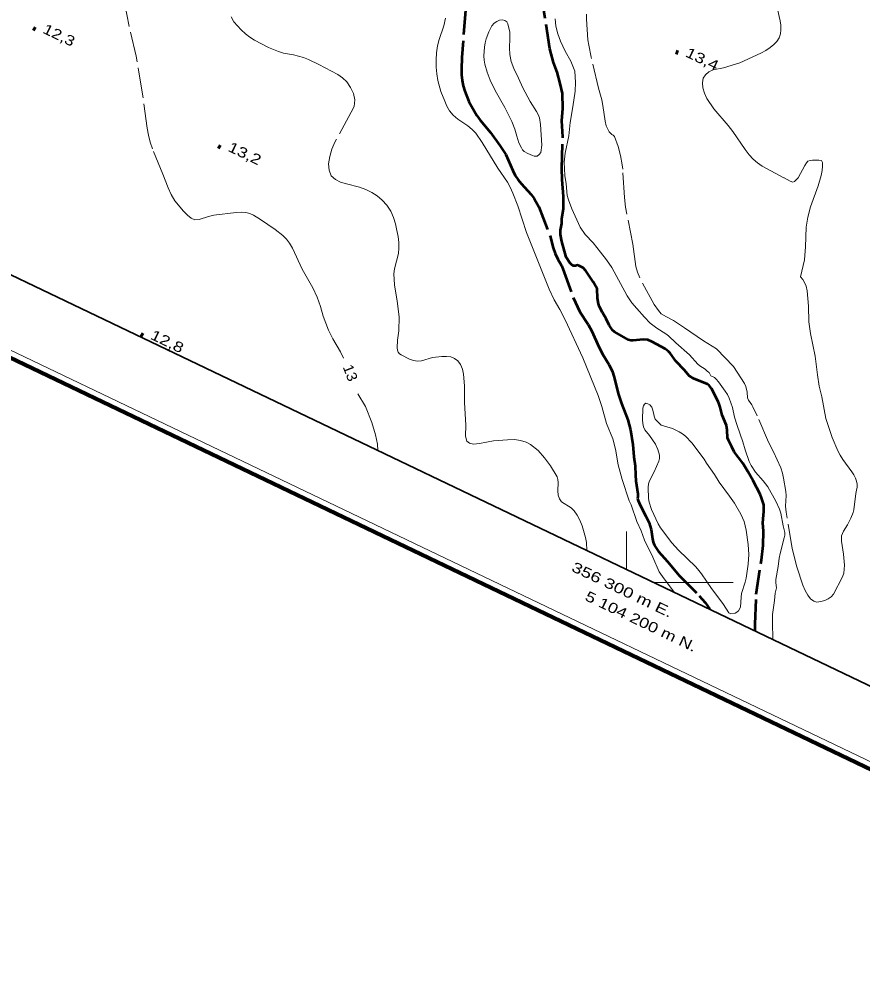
# Model space of a CAD drawing. Extents: x 355726 to 357533, y 5103782 to 5105258.
# Drawn here: x 356210.9 to 356334.6, y 5104143.5 to 5104282.7 of the extents above; entities that cross this region are included whole.
import ezdxf
from ezdxf.enums import TextEntityAlignment as Align

# ---------------------------------------------------------------- set-up
doc = ezdxf.new("R2010")
doc.units = 0
doc.header["$LTSCALE"] = 0.6
doc.linetypes.add('LONG_DASHED', pattern=[7.5, 6, -1.5])
for name, color, linetype, lineweight in [('1', 7, 'LONG_DASHED', 53), ('2', 7, 'LONG_DASHED', 13), ('3', 7, 'Continuous', 140), ('60', 7, 'Continuous', 13), ('61', 7, 'Continuous', 13)]:
    doc.layers.add(name, color=color, linetype=linetype, lineweight=lineweight)

msp = doc.modelspace()

# ---------------------------------------------------------------- linework, layer by layer
at = {"layer": '1'}
for points in [[(356290.52, 5104252.71), (356290.54, 5104253.4), (356290.78, 5104254.91), (356290.75, 5104256.67), (356290.56, 5104259.13), (356290.53, 5104260.76), (356290.66, 5104265.43), (356290.54, 5104267.75), (356290.65, 5104269.57), (356290.61, 5104271.76), (356290.3, 5104273.26), (356289.86, 5104274.9), (356289.3, 5104276.32), (356288.76, 5104278.34), (356287.53, 5104286.45)], [(356276.37, 5104284), (356275.85, 5104277.04), (356275.79, 5104275.34), (356275.83, 5104274.51), (356275.92, 5104273.68), (356276.07, 5104272.88), (356276.28, 5104272.11), (356276.87, 5104270.62), (356278.06, 5104268.53), (356278.52, 5104267.87), (356280.07, 5104266.05), (356281.44, 5104264.16), (356282.29, 5104262.8), (356283.32, 5104260.49), (356283.69, 5104259.76), (356284.1, 5104259.12), (356284.57, 5104258.55), (356286.03, 5104256.94), (356286.45, 5104256.37), (356287.13, 5104255.15), (356288.81, 5104250.82), (356289.27, 5104249.12), (356289.54, 5104248.32), (356289.94, 5104247.44), (356290.46, 5104246.53), (356290.68, 5104246.05), (356292.2, 5104241.84), (356293.19, 5104239.76), (356294.39, 5104237.87), (356294.94, 5104236.88), (356295.93, 5104234.59), (356296.55, 5104233.46), (356297.48, 5104231.96), (356297.98, 5104230.92), (356298.17, 5104230.3), (356298.82, 5104227.63), (356299.28, 5104226.3), (356300.2, 5104223.9), (356300.58, 5104222.43), (356300.93, 5104220.29), (356301.11, 5104218.48), (356301.3, 5104217.16)], [(356318.91, 5104192.9), (356318.9, 5104193.93), (356319.06, 5104198.3), (356319.81, 5104203.29), (356320.04, 5104205.44), (356320.1, 5104207.55), (356320.03, 5104208.79), (356320.09, 5104209.92), (356320.18, 5104210.45), (356320.14, 5104211.42), (356319.83, 5104212.46), (356319.61, 5104212.99), (356318.58, 5104214.96), (356317.82, 5104216.33), (356317.07, 5104217.51), (356315.82, 5104219.2), (356315.49, 5104219.93), (356314.96, 5104220.9), (356314.85, 5104221.25), (356314.78, 5104222.38), (356314.66, 5104223.07), (356314.03, 5104224.59), (356313.76, 5104225.76), (356313.51, 5104226.48), (356312.47, 5104228.47), (356312.15, 5104228.92), (356311.89, 5104229.11), (356309.83, 5104229.97)], [(356301.3, 5104217.16), (356301.33, 5104215.78), (356301.4, 5104214.93), (356301.67, 5104213.05), (356301.69, 5104212.65), (356301.65, 5104212.3), (356301.98, 5104211.45), (356302.87, 5104209.78), (356303.33, 5104208.79), (356303.64, 5104207.8), (356303.82, 5104206.41), (356303.93, 5104205.95), (356304.14, 5104205.46), (356304.4, 5104205), (356304.73, 5104204.55), (356306.02, 5104203.09), (356307.72, 5104201.04), (356310.68, 5104198.08), (356311.56, 5104197.09), (356312.23, 5104196.09)]]:
    msp.add_lwpolyline(points, dxfattribs=at)
at = {"layer": '1', "linetype": 'Continuous'}
msp.add_lwpolyline([(356309.83, 5104229.97), (356309.23, 5104230.34), (356308.53, 5104231.19), (356307.26, 5104232.49), (356306.41, 5104233.65), (356306.17, 5104233.91), (356305.69, 5104234.3), (356303.79, 5104235.34), (356303.15, 5104235.63), (356302.45, 5104235.66), (356301, 5104235.51), (356300.65, 5104235.55), (356300.33, 5104235.65), (356298.27, 5104236.79), (356297.97, 5104237.04), (356297.47, 5104237.78), (356297.05, 5104238.72), (356296.49, 5104239.63), (356296.05, 5104240.48), (356295.91, 5104240.9), (356295.75, 5104241.73), (356295.7, 5104243.13), (356295.12, 5104244.16), (356294.05, 5104245.75), (356293.65, 5104246.19), (356293.05, 5104246.51), (356292.8, 5104246.57), (356292.51, 5104246.49), (356292.22, 5104246.49), (356291.97, 5104246.63), (356291.69, 5104246.91), (356291.18, 5104247.78), (356290.55, 5104250.05), (356290.35, 5104251.07), (356290.34, 5104251.71), (356290.52, 5104252.71)], dxfattribs=at)
at = {"layer": '2'}
for points in [[(356258.48, 5104232.94), (356258.06, 5104233.88), (356256.94, 5104235.76), (356256.28, 5104237.05), (356255.51, 5104239.09), (356255.11, 5104240.51), (356254.64, 5104241.9), (356254.01, 5104243.24), (356252.45, 5104246.01), (356251.01, 5104249.09), (356250.59, 5104249.8), (356250.11, 5104250.4), (356249.58, 5104250.92), (356248.46, 5104251.83), (356246.33, 5104253.3), (356245.3, 5104253.9), (356244.76, 5104254.15), (356244.18, 5104254.3), (356243.52, 5104254.34), (356242.76, 5104254.32), (356239.45, 5104253.9), (356238.69, 5104253.71), (356237.31, 5104253.26), (356236.69, 5104253.22), (356236.14, 5104253.46), (356235.59, 5104253.92), (356235, 5104254.53), (356233.75, 5104256.01), (356233.2, 5104256.96), (356232.76, 5104257.92), (356232.01, 5104259.92), (356230.48, 5104263.63), (356230.14, 5104264.63), (356229.91, 5104265.67), (356229.7, 5104266.7), (356228.98, 5104271.99), (356228.1, 5104277.25), (356227.05, 5104281.59), (356226.34, 5104285.21)], [(356321.91, 5104285.23), (356322.58, 5104282.45), (356322.65, 5104281.78), (356322.66, 5104281.13), (356322.6, 5104280.51), (356322.4, 5104279.94), (356322.08, 5104279.41), (356321.63, 5104278.95), (356321.09, 5104278.51), (356320.43, 5104278.09), (356319.7, 5104277.71), (356316.62, 5104276.25), (356314.24, 5104275.55), (356312.71, 5104275.23), (356312.08, 5104274.96), (356311.59, 5104274.53), (356311.27, 5104274), (356311.16, 5104273.32), (356311.23, 5104272.59), (356311.44, 5104271.83), (356311.8, 5104271.05), (356312.84, 5104269.53), (356314.94, 5104267.09), (356315.61, 5104266.19), (356317.41, 5104263.54), (356318, 5104262.79), (356318.59, 5104262.13), (356319.25, 5104261.59), (356319.93, 5104261.13), (356323.16, 5104259.38), (356324.02, 5104258.93), (356324.41, 5104258.78), (356324.64, 5104258.88), (356324.91, 5104259.08), (356325.19, 5104259.38), (356326.19, 5104261.21), (356326.41, 5104261.58), (356326.64, 5104261.82), (356326.94, 5104261.93), (356327.31, 5104261.98), (356328.25, 5104262.01), (356328.6, 5104261.94), (356328.76, 5104261.63), (356328.79, 5104261.11), (356328.73, 5104260.49), (356328.56, 5104259.76), (356328.12, 5104258.22), (356327.01, 5104255.13), (356326.62, 5104253.63), (356326.38, 5104252.15), (356326.29, 5104249.26), (356326.11, 5104247.38), (356325.52, 5104244.88), (356325.87, 5104244.48), (356326.14, 5104244.05)], [(356241.99, 5104283), (356242.39, 5104282.3), (356243.49, 5104281.09), (356244.11, 5104280.53), (356244.75, 5104280.04), (356245.42, 5104279.61), (356247.49, 5104278.53), (356248.94, 5104277.93), (356249.69, 5104277.71), (356251.18, 5104277.45), (356252.61, 5104277.04), (356253.36, 5104276.74), (356254.86, 5104276.04), (356257.68, 5104274.55), (356258.35, 5104274.09), (356258.96, 5104273.46), (356259.51, 5104272.67), (356259.94, 5104271.75), (356260.15, 5104270.83), (356260.04, 5104269.88), (356259.64, 5104269.01), (356257.23, 5104264.61), (356256.8, 5104263.61), (356256.47, 5104262.53), (356256.31, 5104261.46), (356256.39, 5104260.5)], [(356305.9, 5104239.01), (356305.09, 5104239.46), (356304.7, 5104239.91), (356304.09, 5104240.79), (356301.96, 5104244.74), (356301.63, 5104245.55), (356301.38, 5104246.38), (356300.92, 5104249.66), (356299.88, 5104255.11), (356299.73, 5104256.53), (356299.46, 5104260.65), (356299.39, 5104261.3), (356299.11, 5104262.66), (356298.77, 5104264.01), (356298.26, 5104265.44), (356298.07, 5104265.66), (356297.85, 5104265.78), (356297.47, 5104266.17), (356297.05, 5104267.05), (356296.87, 5104267.7), (356296.54, 5104270.03), (356296.37, 5104270.86), (356295.92, 5104272.55), (356294.85, 5104277.09), (356294.48, 5104278.84), (356294.36, 5104279.66), (356294.12, 5104282.68), (356294.15, 5104283.4)], [(356256.39, 5104260.5), (356256.7, 5104259.71), (356257.31, 5104259.15), (356258.06, 5104258.78), (356258.92, 5104258.5), (356260.82, 5104258.01), (356261.78, 5104257.7), (356262.64, 5104257.26), (356263.44, 5104256.75), (356264.19, 5104256.13), (356264.87, 5104255.38), (356265.43, 5104254.51), (356265.82, 5104253.59), (356266.13, 5104252.63), (356266.34, 5104251.68), (356266.51, 5104250.78), (356266.6, 5104249.91), (356266.62, 5104249.07), (356266.58, 5104248.29), (356266, 5104246.05), (356265.9, 5104245.29), (356265.96, 5104243.7), (356266.37, 5104241.3), (356266.64, 5104239.01), (356266.63, 5104236.95), (356266.44, 5104235.59), (356266.36, 5104234.47), (356266.41, 5104234.09), (356266.53, 5104233.82), (356266.7, 5104233.59), (356266.95, 5104233.45), (356268.19, 5104232.8), (356268.76, 5104232.58), (356269.37, 5104232.49), (356269.92, 5104232.53), (356271.57, 5104233.04), (356272.9, 5104233.19), (356273.61, 5104233.2), (356274.25, 5104233.13), (356274.79, 5104232.88), (356275.25, 5104232.53), (356275.65, 5104232.03), (356275.94, 5104231.34), (356276.11, 5104230.57), (356276.24, 5104228.86), (356276.26, 5104226.43), (356276.43, 5104223.12), (356276.4, 5104221.49), (356276.6, 5104220.76), (356276.96, 5104220.48), (356277.58, 5104220.34), (356278.44, 5104220.43), (356280.48, 5104220.8), (356282.54, 5104220.98), (356283.56, 5104220.99), (356284.46, 5104220.87), (356285.27, 5104220.63), (356285.92, 5104220.25), (356287.04, 5104219.37), (356287.98, 5104218.3), (356288.88, 5104217.12), (356289.86, 5104215.54), (356289.96, 5104215.16), (356290, 5104214.69), (356289.94, 5104213.49), (356290, 5104212.86), (356290.18, 5104212.32), (356290.49, 5104211.88), (356291.89, 5104211), (356292.34, 5104210.53), (356292.77, 5104209.91), (356293.16, 5104209.17), (356293.5, 5104208.34), (356294.01, 5104206.65), (356294.14, 5104205.88), (356294.19, 5104204.73)], [(356326.14, 5104244.05), (356326.37, 5104243.49), (356326.52, 5104242.82), (356326.71, 5104240.57), (356326.78, 5104238.29), (356327.01, 5104236.58), (356327.68, 5104233.21), (356328.02, 5104230.51), (356328.3, 5104228.84), (356328.65, 5104227.28), (356329.27, 5104224.09), (356330.21, 5104221.28), (356331.04, 5104219.36), (356331.36, 5104218.71), (356331.76, 5104218.09), (356333.08, 5104216.24), (356333.34, 5104215.8), (356333.59, 5104215.34), (356333.75, 5104214.9), (356333.83, 5104214.44), (356333.84, 5104214), (356333.78, 5104213.55), (356333.67, 5104213.08), (356333.36, 5104210.68), (356333.27, 5104210.3), (356332.91, 5104209.47), (356332.42, 5104208.5), (356331.86, 5104207.55), (356331.57, 5104206.88), (356331.54, 5104206.49), (356331.57, 5104206.07), (356331.86, 5104204.2), (356331.98, 5104202.58), (356331.89, 5104201.41), (356331.72, 5104200.84), (356330.37, 5104198.3), (356330.05, 5104197.92), (356329.61, 5104197.63), (356329.09, 5104197.4), (356328.52, 5104197.22), (356327.95, 5104197.13), (356327.49, 5104197.3), (356327.02, 5104197.65), (356326.6, 5104198.16), (356326.22, 5104198.84), (356325.88, 5104199.63), (356325.01, 5104202.3), (356324.3, 5104205.03), (356323.44, 5104210.34), (356323.36, 5104211.23), (356323.43, 5104212.78), (356323.4, 5104213.37), (356323.07, 5104215.34), (356322.9, 5104216.09), (356322.64, 5104216.86), (356321.59, 5104219.18), (356320.85, 5104220.62), (356319.19, 5104224.46), (356318.57, 5104225.79), (356318.42, 5104226.08), (356317.9, 5104226.8), (356317.78, 5104227.12), (356317.7, 5104227.93), (356317.52, 5104228.76), (356317.34, 5104229.22), (356315.7, 5104231.72), (356313.2, 5104234.33)], [(356263.55, 5104219.4), (356263.46, 5104220.3), (356263.21, 5104221.68), (356262.64, 5104223.5), (356261.73, 5104225.84), (356260.62, 5104227.73)]]:
    msp.add_lwpolyline(points, dxfattribs=at)
at = {"layer": '2', "linetype": 'Continuous'}
for points in [[(356273.45, 5104282.84), (356273.19, 5104281.69), (356272.54, 5104279.69), (356272.3, 5104278.76), (356272.15, 5104277.75), (356272.09, 5104276.7), (356272.09, 5104275.65), (356272.18, 5104274.65), (356272.35, 5104273.7), (356272.77, 5104272.07), (356273.34, 5104270.63), (356273.67, 5104269.9), (356274.05, 5104269.21), (356274.58, 5104268.58), (356275.25, 5104268), (356276.72, 5104267.01), (356277.37, 5104266.51), (356277.93, 5104265.94), (356278.84, 5104264.57), (356281.13, 5104260.84), (356282.54, 5104258.76), (356282.96, 5104258.01), (356283.34, 5104257.17), (356284.05, 5104255.3), (356285.34, 5104251.38), (356288.66, 5104243.07), (356289.39, 5104241.5), (356290.23, 5104240.08), (356291.01, 5104238.57), (356293.62, 5104233.01), (356295.86, 5104227.45), (356296.41, 5104225.87), (356297.09, 5104223.37), (356298, 5104221.09), (356298.39, 5104219.57), (356298.81, 5104217.28), (356299.37, 5104215.15), (356300.38, 5104212.03), (356300.69, 5104211.4), (356301.53, 5104208.96), (356302.16, 5104207.62), (356302.65, 5104206.24), (356303.89, 5104203.72), (356304.8, 5104201.59), (356305.52, 5104200.55), (356307.04, 5104198.58)], [(356321.49, 5104191.67), (356321.41, 5104194.2), (356321.42, 5104195.34), (356321.73, 5104197.36), (356321.84, 5104198.46), (356322.02, 5104199.26), (356321.93, 5104199.97), (356321.93, 5104200.48), (356322.27, 5104202.36), (356322.4, 5104203.59), (356322.54, 5104204.29), (356323.13, 5104206.57), (356323.22, 5104206.99), (356323.24, 5104207.37), (356322.98, 5104208.34), (356322.65, 5104210.18), (356322.46, 5104210.79), (356321.93, 5104211.97), (356320.75, 5104214.05), (356320.04, 5104214.96), (356318.94, 5104216.23), (356318.28, 5104217.21), (356318.02, 5104217.76), (356317.41, 5104219.49), (356317.06, 5104220.68), (356316.25, 5104223.07), (356315.88, 5104224.3), (356315.54, 5104225.72), (356315.07, 5104227.05), (356314.81, 5104227.59), (356314.5, 5104228.08), (356313.49, 5104229.49), (356313.17, 5104229.84), (356312.91, 5104230.08), (356312.4, 5104230.37), (356312.14, 5104230.83), (356311.92, 5104230.97), (356311.53, 5104231.34), (356310.76, 5104231.8), (356310.48, 5104232.05), (356309.25, 5104233.43), (356307.27, 5104235.18), (356306.19, 5104236.23), (356305.79, 5104236.53), (356304.44, 5104237.34), (356303.5, 5104238.05), (356302.63, 5104238.94), (356301.54, 5104240.25), (356300.78, 5104241.08), (356300.13, 5104242.08), (356297.86, 5104246.23), (356297.06, 5104247.38), (356296.22, 5104248.48), (356295.1, 5104249.84), (356293.95, 5104251.09), (356293.21, 5104252.18), (356291.98, 5104254.87), (356291.48, 5104256.17), (356291.31, 5104256.8), (356291.15, 5104258.51), (356290.97, 5104259.73), (356290.89, 5104261.69), (356291.03, 5104263.03), (356291.56, 5104265.55), (356291.76, 5104267.54), (356292.16, 5104269.8), (356292.48, 5104272.09), (356292.55, 5104273.38), (356292.41, 5104275.07), (356291.84, 5104276.5), (356291.02, 5104277.97), (356290.32, 5104279.45), (356289.93, 5104280.51), (356289.66, 5104281.65), (356289.57, 5104282.75)], [(356313.2, 5104234.33), (356311.3, 5104235.48), (356308.52, 5104237.4), (356306.9, 5104238.45), (356305.9, 5104239.01)]]:
    msp.add_lwpolyline(points, dxfattribs=at)
for points in [[(356287.59, 5104264.21), (356287.41, 5104267.21), (356287.23, 5104268.22), (356287.06, 5104268.67), (356286.81, 5104269.15), (356285.9, 5104270.59), (356284.79, 5104272.59), (356284.16, 5104274.01), (356283.46, 5104275.43), (356283.07, 5104276.46), (356282.91, 5104277.5), (356282.85, 5104278.49), (356282.92, 5104279.86), (356282.9, 5104280.76), (356282.6, 5104281.99), (356282.44, 5104282.3), (356282.17, 5104282.5), (356281.81, 5104282.57), (356281.4, 5104282.51), (356280.99, 5104282.34), (356280.59, 5104282.08), (356280.27, 5104281.72), (356279.83, 5104280.84), (356279.44, 5104279.78), (356279.29, 5104279.2), (356279.16, 5104278.58), (356279.07, 5104277.3), (356279.11, 5104276.68), (356279.22, 5104276.08), (356279.55, 5104274.88), (356280.02, 5104273.74), (356280.76, 5104272.21), (356282.18, 5104269.73), (356283.19, 5104267.65), (356283.61, 5104266.55), (356283.9, 5104265.51), (356284.24, 5104264.55), (356284.59, 5104263.78), (356284.77, 5104263.49), (356284.99, 5104263.28), (356285.56, 5104262.97), (356286.22, 5104262.69), (356286.48, 5104262.59), (356286.9, 5104262.59), (356287.21, 5104262.8), (356287.45, 5104263.13)], [(356305.11, 5104223.13), (356306.77, 5104222.62), (356307.74, 5104222.15), (356308.21, 5104221.86), (356308.66, 5104221.49), (356309.58, 5104220.53), (356311.39, 5104218.11), (356311.75, 5104217.51), (356312.92, 5104215.86), (356313.62, 5104214.75), (356315.14, 5104212.71), (356315.87, 5104211.65), (356316.79, 5104210.03), (356317.26, 5104208.95), (356317.58, 5104207.71), (356317.84, 5104205.59), (356317.95, 5104204.13), (356317.88, 5104202.69), (356317.57, 5104200.65), (356317.43, 5104200.05), (356316.9, 5104198.4), (356316.83, 5104197.87), (356316.76, 5104196.42), (356316.44, 5104195.86), (356316.22, 5104195.66), (356315.95, 5104195.51), (356315.34, 5104195.44), (356315.05, 5104195.55), (356314.24, 5104196.82), (356313.58, 5104197.74), (356312.47, 5104199.13), (356311.02, 5104201.29), (356310.61, 5104201.8), (356310.18, 5104202.3), (356307.63, 5104204.76), (356306.64, 5104205.84), (356305.01, 5104208.05), (356304.68, 5104208.61), (356303.68, 5104210.75), (356303.33, 5104211.8), (356303.25, 5104212.37), (356303.18, 5104213.98), (356303.22, 5104214.49), (356303.38, 5104214.94), (356304.06, 5104216.24), (356304.74, 5104217.82), (356304.84, 5104218.24), (356304.84, 5104218.71), (356304.63, 5104219.55), (356304.27, 5104220.3), (356303.39, 5104221.57), (356302.71, 5104222.42), (356302.5, 5104222.88), (356302.39, 5104223.37), (356302.35, 5104223.91), (356302.42, 5104225.58), (356302.5, 5104225.95), (356302.63, 5104226.2), (356302.87, 5104226.34), (356303.15, 5104226.26), (356303.44, 5104226.09), (356303.71, 5104225.73), (356303.83, 5104225.48), (356303.99, 5104224.93), (356304.06, 5104224.44), (356304.2, 5104224.01)]]:
    msp.add_lwpolyline(points, close=True, dxfattribs=at)
at = {"layer": '3'}
for p, q in [((356212.95, 5104281.34), (356213.31, 5104281.17)), ((356307.23, 5104277.89), (356307.59, 5104277.72)), ((356240.11, 5104264.04), (356240.47, 5104263.87)), ((356228.75, 5104236.44), (356229.11, 5104236.27))]:
    msp.add_line(p, q, dxfattribs=at)
at = {"layer": '60', "lineweight": 158}
msp.add_lwpolyline([(355725.74, 5104464.62), (357152.72, 5103781.6), (357532.66, 5104575.38), (356105.68, 5105258.4)], close=True, dxfattribs=at)
at = {"layer": '60'}
msp.add_lwpolyline([(355727.1, 5104465.08), (357152.24, 5103782.93), (357531.32, 5104574.91), (356106.18, 5105257.06)], close=True, dxfattribs=at)
at = {"layer": '60', "lineweight": 35}
msp.add_lwpolyline([(355740.43, 5104469.78), (356913.03, 5103908.53), (357283.46, 5104682.46), (356110.86, 5105243.71)], close=True, dxfattribs=at)
at = {"layer": '61'}
for p, q in [((356300, 5104201.95), (356300, 5104207.49)), ((356304.07, 5104200), (356315.65, 5104200))]:
    msp.add_line(p, q, dxfattribs=at)

# ---------------------------------------------------------------- texts
at = {"layer": '2', "width": 1.1}
msp.add_text('13', height=1.5, rotation=290.972, dxfattribs=at).set_placement((356258.8, 5104230.52), align=Align.CENTER)
at = {"layer": '3'}
for s, width, p in [('12,3   ', 1.25, (356214.24, 5104280.72)), ('13,4   ', 1.3, (356308.52, 5104277.26)), ('13,2   ', 1.3, (356241.4, 5104263.4)), ('12,8   ', 1.3, (356230.03, 5104235.82))]:
    msp.add_text(s, height=1.5, rotation=334.423, dxfattribs=dict(at, width=width)).set_placement(p)
at = {"layer": '61'}
for s, width, p in [(' 356 300 m E.', 1.35, (356298.73, 5104198.46)), (' 5 104 200 m N.', 1.3, (356301.5, 5104193.8))]:
    msp.add_text(s, height=1.5, rotation=334.42, dxfattribs=dict(at, width=width)).set_placement(p, align=Align.CENTER)

doc.saveas('drawing.dxf')
